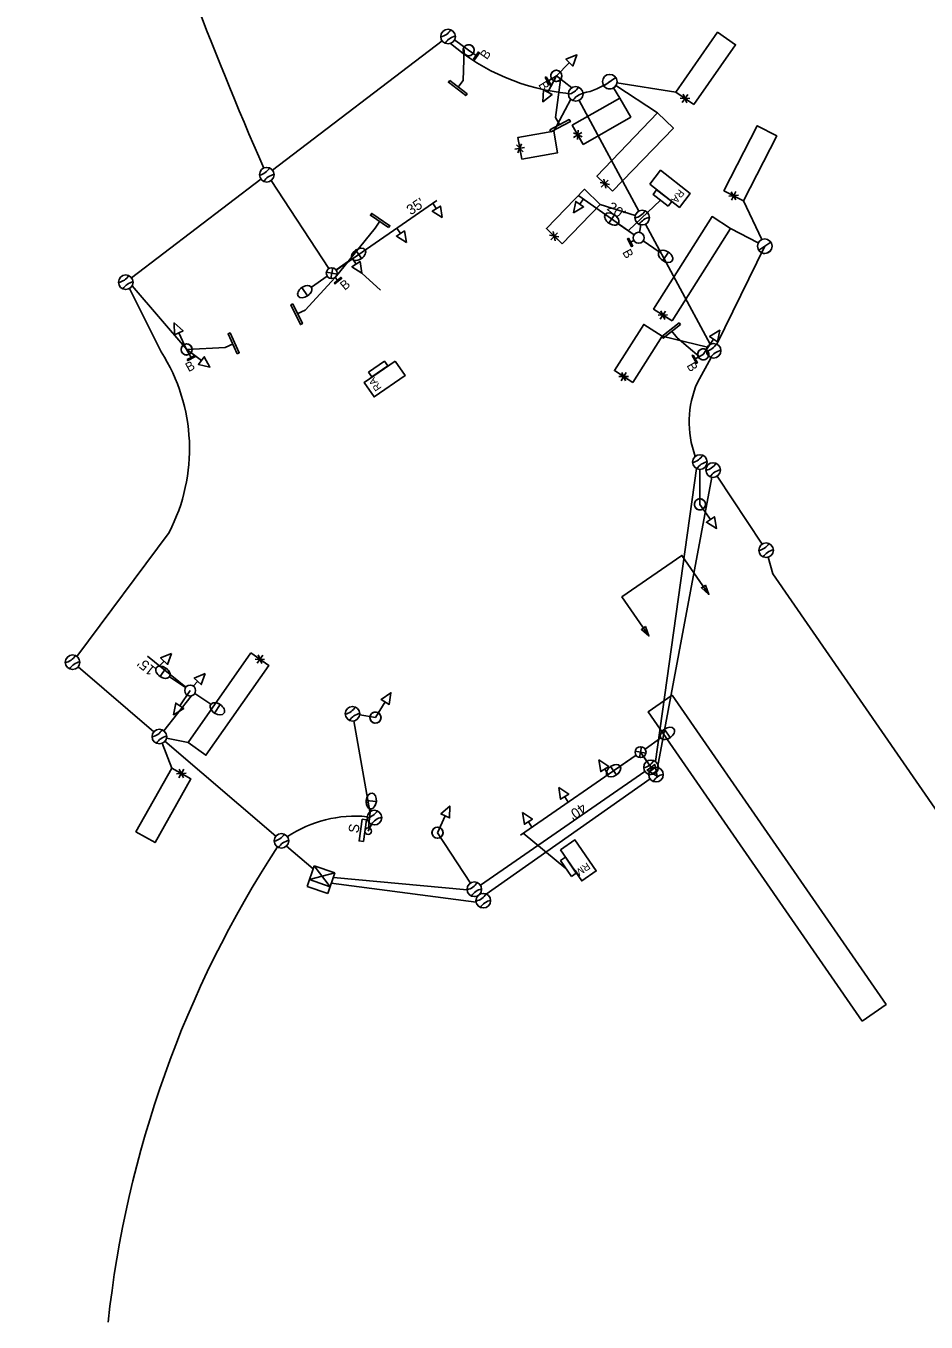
# Model space of a CAD drawing. Extents: x 596176 to 605330, y 332416 to 402398.
# Drawn here: x 602031.8 to 602278.4, y 357338.9 to 357693.9 of the extents above; entities that cross this region are included whole.
import ezdxf

# ---------------------------------------------------------------- set-up
doc = ezdxf.new("R2010")
doc.units = 0
for name, color, linetype in [('P_LTG', 7, 'Continuous'), ('P_SIG', 7, 'Continuous'), ('P_SIG_Bold', 7, 'Continuous'), ('P_SIG_Conduit', 7, 'Continuous'), ('P_SIG_IC', 7, 'Continuous'), ('P_SIG_Loops', 7, 'Continuous')]:
    doc.layers.add(name, color=color, linetype=linetype)

# ---------------------------------------------------------------- blocks, each defined once
blk = doc.blocks.new('_U317')
at = {"layer": 'P_LTG'}
for p, q in [((4.3, 25.1), (-4.1, 25.1)), ((0, 2.3), (0, 18.4))]:
    blk.add_line(p, q, dxfattribs=at)
blk.add_ellipse((0.1, 25.1), major_axis=(0, 6.65), ratio=0.636439, dxfattribs=at)
blk.add_ellipse((0.1, 25.1), major_axis=(0, 6.65), ratio=0.636439, start_param=1.570796, end_param=4.712389, dxfattribs=at)
blk = doc.blocks.new('_U322')
at = {"layer": 'P_LTG'}
for p, q in [((4.3, 25.1), (-4.1, 25.1)), ((0, 2.3), (0, 18.4))]:
    blk.add_line(p, q, dxfattribs=at)
blk.add_ellipse((0.1, 25.1), major_axis=(0, 6.65), ratio=0.636439, dxfattribs=at)
blk.add_ellipse((0.1, 25.1), major_axis=(0, 6.65), ratio=0.636439, start_param=1.570796, end_param=4.712389, dxfattribs=at)
blk = doc.blocks.new('_U225')
at = {"layer": 'P_SIG'}
blk.add_circle((0, 0), 6.1, dxfattribs=at)
for centre, start, end in [((-15.5, 0.1), 336.6741, 22.5272), ((15.5, 0.1), 157.5751, 203.4282)]:
    blk.add_arc(centre, 13.3, start, end, dxfattribs=at)
blk = doc.blocks.new('CONTROL CABINET_8')
at = {"layer": 'P_SIG'}
for p, q in [((-0.229, 0.305), (0.229, 0.305)), ((-0.229, -0.152), (-0.229, 0.305)), ((0.229, 0.305), (0.229, -0.152)), ((-0.229, 0.152), (0.229, 0.152)), ((-0.229, -0.152), (0.229, 0.152)), ((0.229, -0.152), (-0.229, 0.152)), ((0.229, -0.152), (-0.229, -0.152))]:
    blk.add_line(p, q, dxfattribs=at)

msp = doc.modelspace()

# ---------------------------------------------------------------- linework, layer by layer
at = {"layer": 'P_SIG'}
for p, q in [((602151.62, 357678.95), (602151.83, 357687.47)), ((602153.06, 357687.23), (602155.11, 357685.79)), ((602180.65, 357683.85), (602177.11, 357680.24)), ((602151.62, 357678.95), (602150.15, 357677.06)), ((602174.76, 357675.76), (602177.11, 357680.24)), ((602177.11, 357680.24), (602174.99, 357678.92)), ((602176.92, 357668.86), (602178.2, 357679.11)), ((602190.08, 357677.52), (602193.39, 357679.78)), ((602176.92, 357668.86), (602178.02, 357666.72)), ((602183.51, 357645.11), (602184.54, 357646.55)), ((602205.68, 357646.15), (602196.83, 357637.87)), ((602144.22, 357643.87), (602143.25, 357645.35)), ((602116.53, 357625.04), (602127.43, 357638.49)), ((602127.43, 357638.49), (602128.78, 357640.47)), ((602134.38, 357637.07), (602133.41, 357638.55)), ((602198.33, 357635.16), (602197.45, 357634.69)), ((602232.56, 357632.46), (602235.86, 357634.72)), ((602122.22, 357628.65), (602121.25, 357630.13)), ((602108.25, 357616.09), (602116.53, 357625.04)), ((602116.53, 357625.04), (602117.17, 357624.27)), ((602128.92, 357621.52), (602123.84, 357626.17)), ((602108.25, 357616.09), (602106.09, 357615.05)), ((602210.19, 357608.51), (602208.7, 357610.39)), ((602073.65, 357609.87), (602075.81, 357605.3)), ((602086.4, 357605.87), (602088.57, 357606.88)), ((602210.19, 357608.51), (602216.27, 357603.34)), ((602220.2, 357608.13), (602217.35, 357603.96)), ((602075.81, 357605.28), (602077.03, 357603.1)), ((602086.4, 357605.87), (602075.83, 357605.31)), ((602079.86, 357602.24), (602075.83, 357605.31)), ((602217.35, 357603.96), (602215.18, 357602.72)), ((602219.31, 357558.71), (602216.44, 357562.87)), ((602069.64, 357519.92), (602068.43, 357518.63)), ((602078.85, 357514.4), (602077.63, 357513.11)), ((602073.93, 357507.7), (602076.79, 357511.88)), ((602130.22, 357508.77), (602127.55, 357504.47)), ((602203.04, 357490.83), (602200.17, 357495)), ((602190.37, 357490.38), (602191.32, 357488.88)), ((602179.39, 357482.79), (602180.34, 357481.3)), ((602123.05, 357470.68), (602123.93, 357476.62)), ((602123.93, 357476.62), (602125.11, 357476.44)), ((602125.11, 357476.44), (602124.24, 357470.51)), ((602146.67, 357477.53), (602144.56, 357472.93)), ((602169.46, 357475.94), (602170.41, 357474.45)), ((602179.75, 357463.13), (602167.98, 357472.77)), ((602124.24, 357470.51), (602123.05, 357470.68)), ((602108.81, 357458.19), (602110.75, 357463.86)), ((602116.42, 357461.92), (602109.45, 357460.08)), ((602110.75, 357463.86), (602116.42, 357461.92)), ((602110.75, 357463.86), (602115.13, 357458.14)), ((602116.42, 357461.92), (602114.48, 357456.24)), ((602114.48, 357456.24), (602108.81, 357458.19)), ((602115.13, 357458.14), (602109.45, 357460.08))]:
    msp.add_line(p, q, dxfattribs=at)
for points in [[(602154.42, 357684.81), (602155.8, 357686.78), (602156.07, 357686.59), (602154.69, 357684.62)], [(602147.89, 357678.97), (602152.64, 357675.3), (602152.27, 357674.83), (602147.52, 357678.5)], [(602174.36, 357679.94), (602175.62, 357677.9), (602175.35, 357677.73), (602174.08, 357679.77)], [(602175.33, 357665.48), (602180.66, 357668.25), (602180.94, 357667.71), (602175.61, 357664.95)], [(602202.68, 357650.57), (602210.83, 357644.19), (602213.8, 357647.99), (602205.66, 357654.37)], [(602181.81, 357642.69), (602182.44, 357645.87), (602184.59, 357644.35)], [(602207.76, 357644.52), (602208.74, 357645.78), (602204.59, 357649.03), (602203.6, 357647.77)], [(602131.15, 357638.71), (602126.18, 357642.07), (602126.52, 357642.56), (602131.49, 357639.2)], [(602145.84, 357641.4), (602143.12, 357643.15), (602145.33, 357644.59)], [(602136.01, 357634.59), (602133.28, 357636.34), (602135.49, 357637.79)], [(602196.88, 357635.75), (602198.02, 357633.63), (602197.73, 357633.48), (602196.59, 357635.59)], [(602123.84, 357626.17), (602121.12, 357627.93), (602123.32, 357629.37)], [(602116.24, 357623.5), (602118.09, 357625.03), (602118.3, 357624.78), (602116.45, 357623.25)], [(602104.93, 357617.77), (602107.53, 357612.37), (602106.99, 357612.11), (602104.39, 357617.51)], [(602211.1, 357612.12), (602206.4, 357608.39), (602206.03, 357608.86), (602210.73, 357612.59)], [(602089.7, 357604.14), (602087.17, 357609.58), (602087.71, 357609.84), (602090.24, 357604.39)], [(602075.98, 357602.51), (602078.08, 357603.68), (602078.23, 357603.4), (602076.14, 357602.23)], [(602214.59, 357603.77), (602215.77, 357601.68), (602215.49, 357601.52), (602214.3, 357603.61)], [(602132.94, 357602.13), (602124.43, 357596.24), (602127.18, 357592.28), (602135.69, 357598.17)], [(602125.66, 357599.08), (602126.57, 357597.76), (602130.91, 357600.77), (602130, 357602.08)], [(602217.94, 357540.76), (602218.91, 357538.2), (602216.86, 357540.01)], [(602201.5, 357529.38), (602202.46, 357526.82), (602200.41, 357528.63)], [(602071.68, 357522.06), (602070.6, 357519.01), (602068.69, 357520.83)], [(602080.89, 357516.54), (602079.81, 357513.49), (602077.9, 357515.31)], [(602188.78, 357492.87), (602191.48, 357491.08), (602189.26, 357489.67)], [(602177.8, 357485.29), (602180.5, 357483.5), (602178.27, 357482.09)], [(602124.24, 357470.51), (602123.05, 357470.68), (602123.93, 357476.62), (602125.11, 357476.44)], [(602167.87, 357478.44), (602170.57, 357476.65), (602168.35, 357475.23)], [(602178.21, 357468.25), (602184.08, 357459.73), (602188.05, 357462.46), (602182.18, 357470.98)], [(602181.25, 357460.96), (602182.57, 357461.87), (602179.57, 357466.21), (602178.26, 357465.3)]]:
    msp.add_lwpolyline(points, close=True, dxfattribs=at)
for points in [[(602182.72, 357685.97), (602181.6, 357682.93), (602179.71, 357684.77), (602182.72, 357685.97)], [(602181.6, 357682.93), (602182.72, 357685.97), (602179.71, 357684.77), (602181.6, 357682.93)], [(602193.39, 357679.78), (602190.08, 357677.52)], [(602173.39, 357673.14), (602173.6, 357676.37), (602175.93, 357675.15), (602173.39, 357673.14)], [(602173.6, 357676.37), (602173.39, 357673.14), (602175.93, 357675.15), (602173.6, 357676.37)], [(602235.86, 357634.72), (602232.56, 357632.46)], [(602072.38, 357612.55), (602074.84, 357610.44), (602072.46, 357609.31), (602072.38, 357612.55)], [(602074.84, 357610.44), (602072.38, 357612.55), (602072.46, 357609.31), (602074.84, 357610.44)], [(602221.87, 357610.58), (602221.29, 357607.4), (602219.11, 357608.88), (602221.87, 357610.58)], [(602221.29, 357607.4), (602221.87, 357610.58), (602219.11, 357608.88), (602221.29, 357607.4)], [(602082.22, 357600.46), (602079.06, 357601.19), (602080.65, 357603.3), (602082.22, 357600.46)], [(602082.22, 357600.46), (602079.06, 357601.19), (602080.65, 357603.3), (602082.22, 357600.46)], [(602079.06, 357601.19), (602082.22, 357600.46), (602080.65, 357603.3), (602079.06, 357601.19)], [(602221, 357556.28), (602218.23, 357557.96), (602220.4, 357559.46), (602221, 357556.28)], [(602218.23, 357557.96), (602221, 357556.28), (602220.4, 357559.46), (602218.23, 357557.96)], [(602131.78, 357511.29), (602131.34, 357508.08), (602129.1, 357509.46), (602131.78, 357511.29)], [(602131.34, 357508.08), (602131.78, 357511.29), (602129.1, 357509.46), (602131.34, 357508.08)], [(602072.26, 357505.26), (602072.84, 357508.44), (602075.02, 357506.96), (602072.26, 357505.26)], [(602072.26, 357505.26), (602072.84, 357508.44), (602075.02, 357506.96), (602072.26, 357505.26)], [(602072.84, 357508.44), (602072.26, 357505.26), (602075.02, 357506.96), (602072.84, 357508.44)], [(602204.73, 357488.4), (602201.96, 357490.08), (602204.13, 357491.59), (602204.73, 357488.4)], [(602204.73, 357488.4), (602201.96, 357490.08), (602204.13, 357491.59), (602204.73, 357488.4)], [(602201.96, 357490.08), (602204.73, 357488.4), (602204.13, 357491.59), (602201.96, 357490.08)], [(602147.9, 357480.22), (602147.87, 357476.98), (602145.47, 357478.07), (602147.9, 357480.22)], [(602147.87, 357476.98), (602147.9, 357480.22), (602145.47, 357478.07), (602147.87, 357476.98)]]:
    msp.add_lwpolyline(points, dxfattribs=at)
for centre, radius in [((602147.44, 357691.01), 2), ((602153.06, 357687.25), 1.52), ((602177.11, 357680.24), 1.52), ((602177.11, 357680.24), 1.52), ((602177.11, 357680.24), 1.52), ((602177.11, 357680.24), 1.52), ((602177.11, 357680.24), 1.52), ((602177.11, 357680.24), 1.52), ((602191.74, 357678.65), 2), ((602182.41, 357675.3), 2), ((602097.77, 357653.16), 2), ((602200.62, 357641.41), 2), ((602234.21, 357633.59), 2), ((602059.16, 357623.72), 2), ((602075.81, 357605.3), 1.52), ((602075.81, 357605.3), 1.52), ((602075.81, 357605.3), 1.52), ((602220.2, 357604.95), 2), ((602217.35, 357603.96), 1.52), ((602217.35, 357603.96), 1.52), ((602217.35, 357603.96), 1.52), ((602216.42, 357574.46), 2), ((602216.44, 357562.87), 1.52), ((602216.44, 357562.87), 1.52), ((602216.44, 357562.87), 1.52), ((602044.56, 357519.63), 2), ((602121.26, 357505.52), 2), ((602127.55, 357504.47), 1.52), ((602127.55, 357504.47), 1.52), ((602127.55, 357504.47), 1.52), ((602068.35, 357499.28), 2), ((602203.05, 357490.84), 2), ((602127.26, 357477.07), 2), ((602101.8, 357470.71), 2), ((602125.57, 357473.35), 0.9), ((602144.56, 357472.93), 1.52), ((602144.56, 357472.93), 1.52), ((602144.56, 357472.93), 1.52), ((602154.64, 357457.44), 2)]:
    msp.add_circle(centre, radius, dxfattribs=at)
for centre, radius, start, end in [((602144.52, 357695.16), 4.36, 282.2572, 328.1103), ((602150.3, 357686.82), 4.36, 101.3562, 147.2093), ((602153.06, 357687.25), 1.52, 141.2809, 321.2809), ((602153.06, 357687.25), 1.52, 321.2809, 141.2809), ((602177.11, 357680.24), 1.52, 45.745, 225.745), ((602177.11, 357680.24), 1.52, 62.4257, 242.4257), ((602177.11, 357680.24), 1.52, 225.745, 45.745), ((602177.11, 357680.24), 1.52, 242.4257, 62.4257), ((602191.74, 357678.65), 2, 214.3829, 304.6821), ((602191.74, 357678.65), 2, 304.6821, 34.3829), ((602179.49, 357679.44), 4.36, 282.2572, 328.1103), ((602185.27, 357671.11), 4.36, 101.3562, 147.2093), ((602094.85, 357657.31), 4.36, 282.2572, 328.1103), ((602100.63, 357648.97), 4.36, 101.3562, 147.2093), ((602197.69, 357645.55), 4.36, 282.2572, 328.1103), ((602203.47, 357637.22), 4.36, 101.3562, 147.2093), ((602234.21, 357633.59), 2, 214.3829, 304.6821), ((602234.21, 357633.59), 2, 304.6821, 34.3829), ((602056.24, 357627.86), 4.36, 282.2572, 328.1103), ((602062.02, 357619.53), 4.36, 101.3562, 147.2093), ((602075.81, 357605.3), 1.52, 115.4556, 295.4556), ((602075.81, 357605.3), 1.52, 295.4556, 115.4556), ((602217.28, 357609.1), 4.36, 282.2572, 328.1103), ((602217.35, 357603.96), 1.52, 55.8447, 235.8447), ((602217.35, 357603.96), 1.52, 235.8447, 55.8447), ((602223.06, 357600.76), 4.36, 101.3562, 147.2093), ((602213.5, 357578.6), 4.36, 282.2572, 328.1103), ((602219.28, 357570.27), 4.36, 101.3562, 147.2093), ((602216.44, 357562.87), 1.52, 124.7799, 304.7799), ((602216.44, 357562.87), 1.52, 304.7799, 124.7799), ((602041.64, 357523.77), 4.36, 282.2572, 328.1103), ((602047.41, 357515.44), 4.36, 101.3562, 147.2093), ((602118.34, 357509.67), 4.36, 282.2572, 328.1103), ((602124.12, 357501.33), 4.36, 101.3562, 147.2093), ((602127.55, 357504.47), 1.52, 58.2953, 238.2953), ((602127.55, 357504.47), 1.52, 238.2953, 58.2953), ((602065.43, 357503.43), 4.36, 282.2572, 328.1103), ((602071.21, 357495.09), 4.36, 101.3562, 147.2093), ((602200.12, 357494.98), 4.36, 282.2572, 328.1103), ((602205.9, 357486.65), 4.36, 101.3562, 147.2093), ((602124.34, 357481.22), 4.36, 282.2572, 328.1103), ((602130.12, 357472.88), 4.36, 101.3562, 147.2093), ((602098.88, 357474.86), 4.36, 282.2572, 328.1103), ((602144.56, 357472.93), 1.52, 65.4556, 245.4556), ((602144.56, 357472.93), 1.52, 245.4556, 65.4556), ((602104.65, 357466.52), 4.36, 101.3562, 147.2093), ((602151.72, 357461.58), 4.36, 282.2572, 328.1103), ((602157.5, 357453.25), 4.36, 101.3562, 147.2093)]:
    msp.add_arc(centre, radius, start, end, dxfattribs=at)
at = {"layer": 'P_SIG_Bold'}
for p, q in [((602144.36, 357646.12), (602116.81, 357627.06)), ((602183.31, 357647.42), (602198.42, 357636.74)), ((602117.05, 357625.93), (602114.1, 357626.47)), ((602115.31, 357624.73), (602115.84, 357627.68)), ((602065.12, 357521.31), (602075.62, 357512.82)), ((602065.12, 357521.31), (602075.62, 357512.82)), ((602200.44, 357496.47), (602199.9, 357493.52)), ((602167.25, 357472.27), (602198.93, 357494.14)), ((602198.69, 357495.27), (602201.64, 357494.73))]:
    msp.add_line(p, q, dxfattribs=at)
for centre in [(602199.65, 357635.88), (602115.57, 357626.2), (602076.79, 357511.88), (602076.79, 357511.88), (602200.17, 357495)]:
    msp.add_circle(centre, 1.5, dxfattribs=at)
at = {"layer": 'P_SIG_Conduit'}
for p, q in [((602145.84, 357689.82), (602099.36, 357654.38)), ((602153.06, 357687.25), (602149.21, 357690.08)), ((602096.18, 357651.95), (602060.75, 357624.93)), ((602114.75, 357627.46), (602098.96, 357651.55)), ((602199.91, 357637.35), (602200.27, 357639.44)), ((602075.83, 357605.31), (602060.91, 357622.74)), ((602204.29, 357492.4), (602215.48, 357572.7)), ((602066.83, 357500.59), (602046.08, 357518.33)), ((602069.58, 357500.86), (602077.06, 357510.38)), ((602126.05, 357478.7), (602121.62, 357503.56)), ((602100.28, 357472.01), (602069.88, 357497.99)), ((602126.43, 357475.25), (602125.57, 357473.37)), ((602110.48, 357463.08), (602103.18, 357469.27)), ((602152.65, 357457.29), (602116.01, 357460.71))]:
    msp.add_line(p, q, dxfattribs=at)
for points in [[(602181.32, 357676.97), (602177.11, 357680.24)], [(602199.67, 357643.17), (602183.36, 357673.53)], [(602219.26, 357606.71), (602201.56, 357639.65)], [(602234.26, 357633.56), (602221.08, 357606.75)], [(602060.15, 357621.98), (602068.85, 357604.62)], [(602215.75, 357596.29), (602219.51, 357603.08)], [(602216.44, 357562.87), (602216.43, 357572.46)], [(602071.02, 357555.2), (602045.75, 357521.23)], [(602127.55, 357504.47), (602123.24, 357505.2)], [(602201.91, 357492.48), (602200.15, 357494.98)], [(602156.29, 357458.58), (602201.38, 357489.73)], [(602144.56, 357472.93), (602153.55, 357459.12)]]:
    msp.add_lwpolyline(points, dxfattribs=at)
for centre, radius, start, end in [((603007.09, 358054.64), 994, 191.13156, 203.70692), ((602185.58, 357732.59), 57.38, 229.2368, 264.8316), ((602181.12, 357693.33), 18.11, 280.4245, 305.8769), ((602027.19, 357578.04), 49.42, 332.48, 32.5478), ((602240.88, 357585.4), 27.38, 156.5738, 200.0645), ((602122.05, 357443.79), 33.69, 84.499, 123.5425), ((602348.44, 357307.42), 295.8, 146.8807, 173.8922)]:
    msp.add_arc(centre, radius, start, end, dxfattribs=at)
at = {"layer": 'P_SIG_IC'}
for p, q in [((602219.67, 357570.3), (602204.78, 357490.81)), ((602233.47, 357551.97), (602221.15, 357570.6)), ((602157.92, 357456.13), (602202.77, 357487.69)), ((602155.13, 357453.93), (602115.45, 357459.08))]:
    msp.add_line(p, q, dxfattribs=at)
for points in [[(602236.38, 357543.86), (602235.11, 357548.38)], [(602361.01, 357363.75), (602236.38, 357543.86)]]:
    msp.add_lwpolyline(points, dxfattribs=at)
at = {"layer": 'P_SIG_Loops'}
for p, q in [((602204.84, 357670.09), (602193.41, 357677.56)), ((602193.71, 357678.34), (602209.87, 357675.79)), ((602194.5, 357674.14), (602192.78, 357676.95)), ((602213.64, 357674.05), (602211.04, 357674.11)), ((602211.56, 357672.93), (602213.09, 357675.13)), ((602212.82, 357672.85), (602211.85, 357675.24)), ((602212.33, 357674.07), (602214.79, 357672.35)), ((602176.44, 357665.07), (602181.07, 357673.81)), ((602181.79, 357663.39), (602184.11, 357664.72)), ((602184.15, 357663.5), (602181.83, 357664.67)), ((602182.89, 357662.77), (602183.04, 357665.35)), ((602182.97, 357664.08), (602184.46, 357661.48)), ((602165.75, 357660.15), (602168.38, 357660.61)), ((602168, 357659.45), (602166.22, 357661.35)), ((602166.57, 357659.19), (602167.59, 357661.58)), ((602191.66, 357650.51), (602189.11, 357650.99)), ((602189.43, 357649.74), (602191.29, 357651.67)), ((602190.66, 357649.45), (602190.08, 357651.98)), ((602190.37, 357650.74), (602192.53, 357648.66)), ((602226.98, 357647.54), (602224.39, 357647.25)), ((602226.32, 357646.24), (602225.03, 357648.48)), ((602225.06, 357646.15), (602226.28, 357648.54)), ((602225.67, 357647.38), (602228.34, 357646.01)), ((602233.36, 357635.4), (602228.34, 357646.01)), ((602189.12, 357645.02), (602198.71, 357642.01)), ((602224.86, 357638.47), (602232.44, 357634.52)), ((602177.82, 357636.11), (602175.26, 357636.59)), ((602175.58, 357635.34), (602177.44, 357637.27)), ((602176.81, 357635.06), (602176.23, 357637.58)), ((602176.52, 357636.34), (602178.67, 357634.25)), ((602207.59, 357614.77), (602204.99, 357614.72)), ((602205.55, 357613.56), (602206.99, 357615.83)), ((602206.82, 357613.53), (602205.74, 357615.89)), ((602206.27, 357614.73), (602208.81, 357613.13)), ((602206.13, 357608.92), (602218.48, 357605.97)), ((602196.86, 357597.91), (602194.26, 357597.87)), ((602194.82, 357596.71), (602196.26, 357598.97)), ((602196.09, 357596.67), (602195.01, 357599.03)), ((602195.54, 357597.87), (602198.08, 357596.26)), ((602095.9, 357520.43), (602093.45, 357522.16)), ((602096.68, 357521.56), (602095.14, 357519.37)), ((602095.41, 357521.66), (602096.38, 357519.25)), ((602094.59, 357520.46), (602097.19, 357520.38)), ((602069.08, 357497.42), (602071.76, 357490.6)), ((602076.2, 357497.61), (602070.31, 357498.87)), ((602074.37, 357489.13), (602071.76, 357490.6)), ((602075.03, 357490.33), (602073.72, 357488)), ((602073.77, 357490.3), (602074.97, 357488)), ((602073.06, 357489.03), (602075.66, 357489.2))]:
    msp.add_line(p, q, dxfattribs=at)
for points in [[(602214.79, 357672.35), (602226.23, 357688.76), (602221.3, 357692.19), (602209.87, 357675.79)], [(602184.46, 357661.48), (602197.48, 357668.94), (602194.5, 357674.14), (602181.48, 357666.69)], [(602192.52, 357648.62), (602209.16, 357665.93), (602204.84, 357670.09), (602188.2, 357652.78)], [(602167.61, 357657.45), (602177.46, 357659.16), (602176.44, 357665.07), (602166.58, 357663.36)], [(602228.34, 357646.01), (602237.47, 357663.81), (602232.13, 357666.55), (602223, 357648.75)], [(602178.67, 357634.25), (602189.12, 357645.02), (602184.81, 357649.2), (602174.37, 357638.43)], [(602208.81, 357613.13), (602224.86, 357638.47), (602219.79, 357641.68), (602203.74, 357616.34)], [(602198.08, 357596.26), (602206.13, 357608.92), (602201.07, 357612.14), (602193.01, 357599.49)], [(602093.45, 357522.16), (602076.2, 357497.61), (602081.11, 357494.16), (602098.36, 357518.7)], [(602260.86, 357421.34), (602267.44, 357425.89), (602208.83, 357510.59), (602202.25, 357506.04)], [(602071.76, 357490.6), (602061.93, 357473.18), (602067.16, 357470.23), (602076.99, 357487.65)]]:
    msp.add_lwpolyline(points, close=True, dxfattribs=at)
msp.add_lwpolyline([(602202.47, 357526.82), (602195.07, 357537.51), (602211.51, 357548.89), (602218.91, 357538.2)], dxfattribs=at)

# ---------------------------------------------------------------- block references
at = {"layer": 'P_LTG'}
for name, p, xscale, yscale, rotation in [('_U317', (602199.03, 357636.3), 0.32808333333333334, 0.3280833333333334, 55.157402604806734), ('_U317', (602200.26, 357635.45), 0.32808333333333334, 0.3280833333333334, -124.28450284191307), ('_U317', (602116.18, 357626.63), 0.32808333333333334, 0.3280833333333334, -54.75978083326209), ('_U317', (602114.97, 357625.77), 0.3280833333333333, 0.32808333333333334, 124.68212461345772), ('_U317', (602076.15, 357512.27), 0.32808333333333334, 0.3280833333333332, 56.13780507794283), ('_U317', (602077.42, 357511.48), 0.32808333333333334, 0.3280833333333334, -123.86219492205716), ('_U317', (602200.79, 357495.4), 0.32808333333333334, 0.3280833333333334, -54.75978083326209), ('_U317', (602199.56, 357494.56), 0.3280833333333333, 0.32808333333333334, 124.68212461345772), ('_U322', (602125.56, 357473.43), 0.32808333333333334, 0.3280833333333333, -5.710972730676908)]:
    msp.add_blockref(name, p, dxfattribs=dict(at, xscale=xscale, yscale=yscale, rotation=rotation))
at = {"layer": 'P_SIG_Bold', "xscale": 13.123333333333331, "yscale": 13.12333333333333, "rotation": 161.13235822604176}
msp.add_blockref('CONTROL CABINET_8', (602112.94, 357461), dxfattribs=at)
at = {"layer": 'P_SIG_IC', "xscale": 0.3280833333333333, "yscale": 0.32808333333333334, "rotation": 124.68212461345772}
for p in [(602220.05, 357572.27), (602234.57, 357550.31), (602204.41, 357488.84), (602157.09, 357454.32)]:
    msp.add_blockref('_U225', p, dxfattribs=at)

# ---------------------------------------------------------------- texts
at = {"layer": 'P_SIG'}
for s, height, rotation, p in [('B', 2.52, 55.0066, (602158.06, 357684.52)), ('B', 2.52, 301.8126, (602172.07, 357677.81)), ('RA', 2, 231.9334, (602210.79, 357649.31)), ('B', 2.52, 298.3138, (602195.11, 357631.94)), ('B', 2.52, 39.5715, (602119.14, 357621.35)), ('B', 2.52, 29.1813, (602076.38, 357599.04)), ('B', 2.52, 299.5276, (602212.72, 357600.9)), ('RA', 2, 124.6821, (602129.34, 357594.77)), ('S', 2.8, 81.5767, (602122.87, 357472.68)), ('RM', 2, 214.5631, (602185.5, 357464.9))]:
    msp.add_text(s, height=height, rotation=rotation, dxfattribs=at).set_placement(p)
at = {"layer": 'P_SIG_Bold'}
for s, rotation, p in [("35'", 33.5503, (602137.23, 357641.98)), ("20'", 324.7609, (602190.75, 357643.65)), ("15'", 141.0458, (602067.55, 357517.91)), ("40'", 214.5939, (602184.18, 357481.24))]:
    msp.add_text(s, height=2.8, rotation=rotation, dxfattribs=at).set_placement(p)

doc.saveas('drawing.dxf')
